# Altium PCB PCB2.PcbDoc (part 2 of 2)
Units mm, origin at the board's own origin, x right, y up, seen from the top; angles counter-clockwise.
Board outline 159.99 x 100 mm, 12 copper layers (TopLayer, VCC, GROUND, MidLayer1, MidLayer2, MidLayer3, MidLayer4, MidLayer5, MidLayer6, MidLayer7, MidLayer8, BottomLayer); 300 components, 468 nets, 2269 pads, 42 vias.
Unrouted connection lines stored in the file: 456.
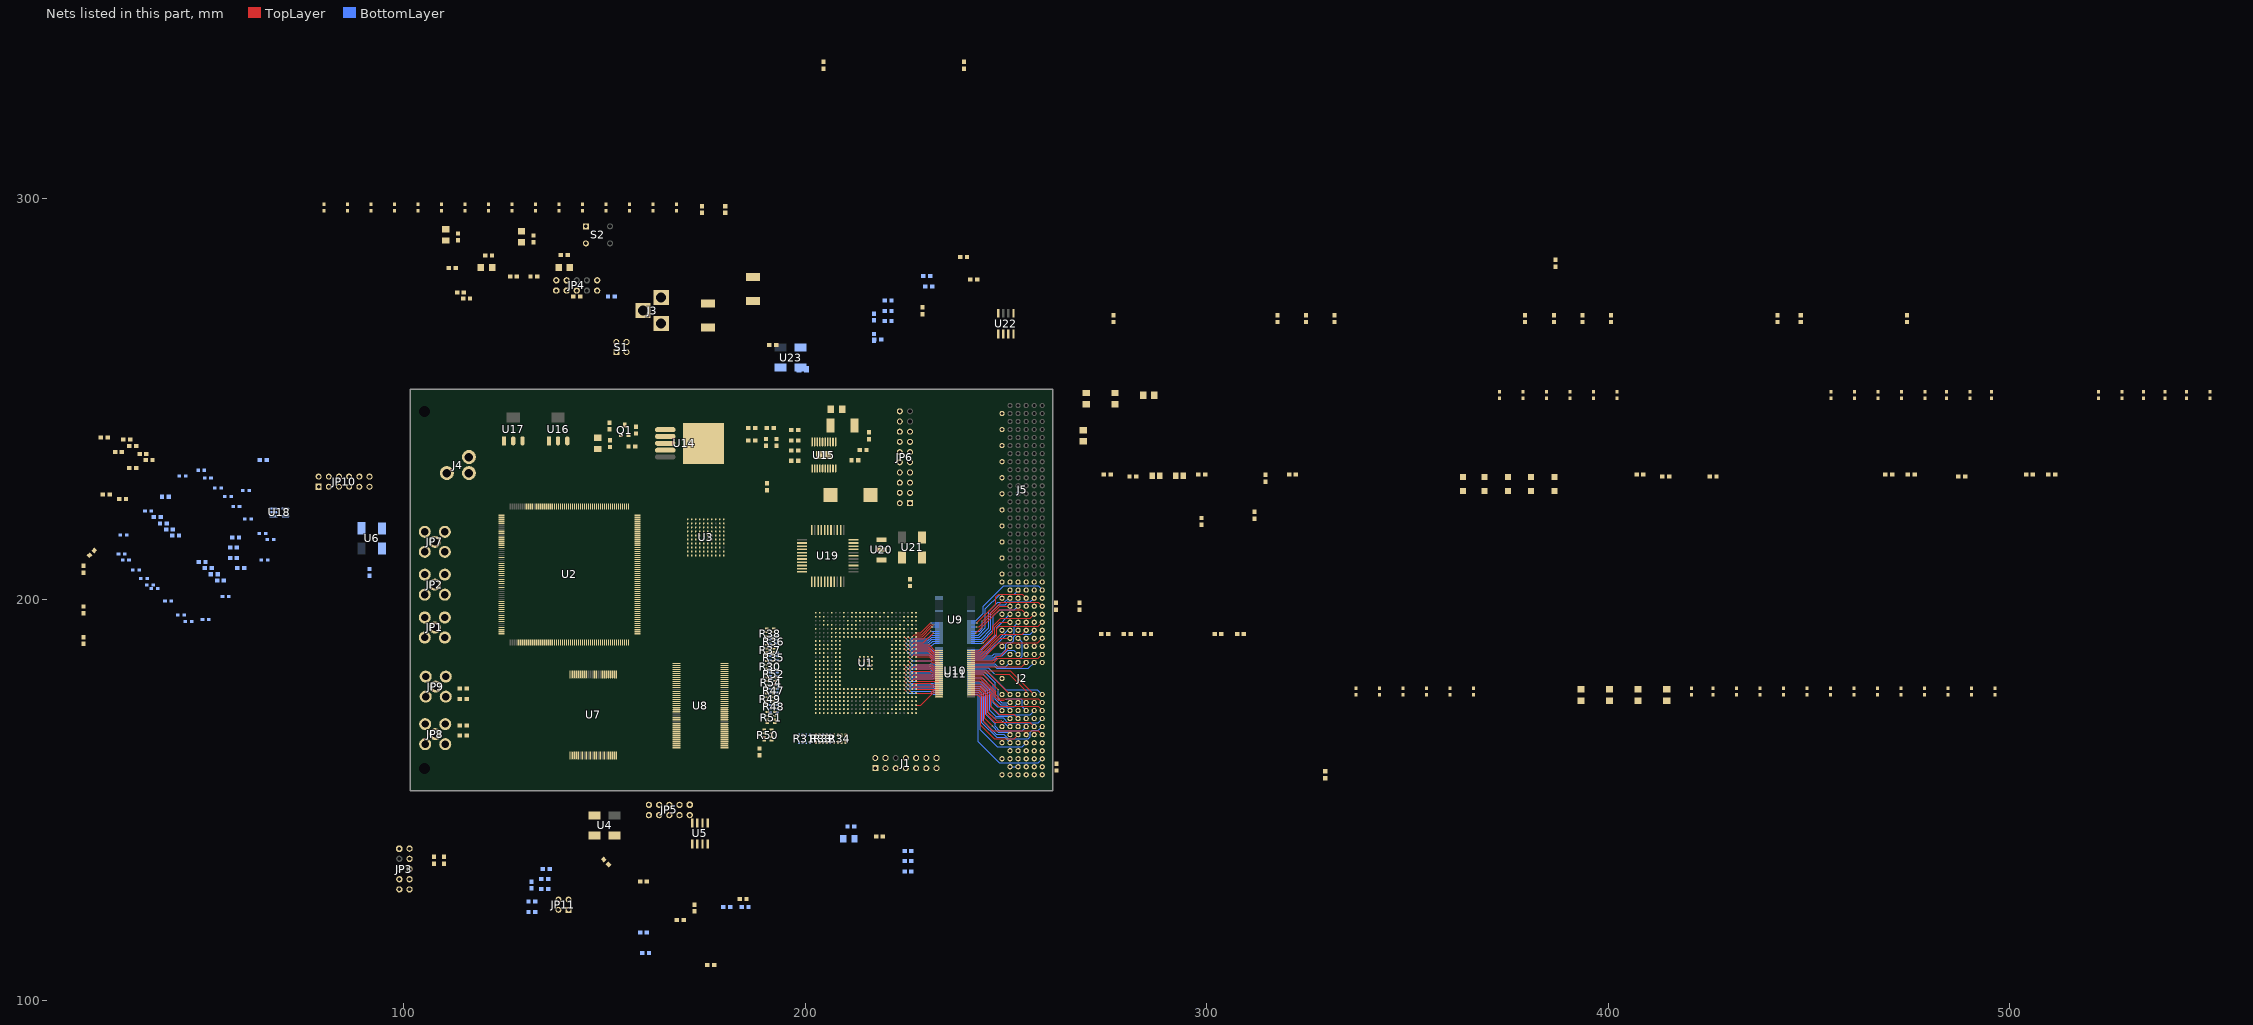
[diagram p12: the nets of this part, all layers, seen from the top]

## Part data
C1 C2 C3 C4 C5 C6 C7 C8 C9 C10 C11 C12 C13 C14 C15 C16 C17 C18 C19 C20 C21 C22 C23 C24 C25 C26 C27 C28 C29 C30 C32 C36 C37 C38 C39 C40 C41 C42 C43 C44 C45 C46 C47 C48 C49 C50 C51 C52 C53 C54 C55 C56 C57 C58 C59 C60 C61 C62 C63 C64 C65 C66 C67 C68 C69 C70 C71 C72 C73 C74 C75 C76 C77 C78 C79 C80 C81 C82 C83 C84 C85 C86 C87 C88 C89 C90 C91 C92 C93 C94 C95 C96 C97 C98 C99 C100 C101 C102 C103 C104 C105 C106 C107 C108 C109 C110 C111 C112 C113 C114 C115 C116 C117 C118 C119 C120 C121 C122 C123 C124 C125 C126 C127 C128 C129 C130 C131 C132 C133 C153 C154 C155 C156 C157 C158 C159 C160 C161 C162 C163 C165 C166: "Capacitor"
C134 C135 C136 C137 C138 C139 C140 C141 C142 C143: "Polarized Capacitor (Radial)"
C144 C145 C146 C147 C148 C149 C150 C151 C152 C164: "Polarized Capacitor (Axial)"
DS1 DS2 DS3 DS4 DS5: "Typical RED, GREEN, YELLOW, AMBER GaAs LED"
DS6 DS7 DS9: "Typical BLUE SiC LED"
FB1 FB2 FB3: library part Inductor, "Inductor"
J1: library part "Header 7X2", "Header, 7-Pin, Dual row"
J2: library part 352495-1, "Z-Pack 2mm Hard Metric Type A 154 Position Male PCB Mount Connector"
J4: "RCA Connector"
J5: "Z-Pack 2mm Hard Metric Type B 110 Position Female Daughter Card Connector"
JP1 JP2 JP7 JP8 JP9: "Header, 2-Pin"
JP3 JP4 JP5: library part "Header 5X2", "Header, 5-Pin, Dual row"
JP6: "Header, 10-Pin, Dual row"
JP10: "Header, 6-Pin, Dual row"
JP11: "Header, 2-Pin, Dual row"
L1: "Magnetic-Core Inductor"
Q1: library part QNPN, "NPN Bipolar Transistor"
R1 R2 R3 R4 R5 R6 R7 R8 R9 R10 R11 R12 R13 R14 R15 R16 R17 R18 R19 R20 R21 R22 R23 R24 R25 R26 R27 R28 R29 R39 R40 R41 R42 R43 R44 R45 R46 R53 R55 R56 R57 R58 R59 R60 R61 R62 R63 R64 R65 R66 R67 R68 R69 R70 R71 R72 R73 R74 R76 R77 R78 R79 R80 R81 R82 R83 R84 R86 R87 R88: "Resistor"
R30 R31 R32 R33 R34 R35 R36 R37 R38 R47 R48 R49 R50 R51 R52 R54: "Resistor Array - Parts"
S1: "DIP Switch"
S2: "Switch"
U2: "Cyclone Family, 1.5V FPGA, 173 I/O Pins, 2 x PLLs, Commercial Grade, Speed Grade 6"
U3: "Hotlink II"
U4 U6: library part Oscillator
U5: "EPCS1 Series, In-system programmable 3.3V configuration device, 8-Pin SOIC, 1-Megabit, Industrial Grade"
U8: "by TX"
U16 U17: library part "Volt Reg", "Voltage Regulator"
U20: library part "EMI filter"

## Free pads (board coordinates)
  round 1.27 hole 2.794: 1(105.156,246.812) 2(105.156,157.912)

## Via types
v1: diameter 0.406, hole 0.203, TopLayer to BottomLayer, 40 vias
v2: diameter 1.44, hole 1.44, TopLayer to BottomLayer, 2 vias

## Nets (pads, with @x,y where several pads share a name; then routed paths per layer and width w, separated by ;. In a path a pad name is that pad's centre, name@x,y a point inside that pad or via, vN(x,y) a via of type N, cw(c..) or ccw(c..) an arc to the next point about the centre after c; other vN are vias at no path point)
1.4VPWRGD: R64.2 R72.2 U15.4
101_BISTLE: U2.12 U3.E1
101_BOE0: U2.14 U3.D1
101_BOE1: U2.15 U3.D2
101_DECOMDE: U2.8 U3.E2
101_FRAMCHAR: U2.13 U3.D3
101_INSEL: U2.195 U3.C10
101_L\F\I\: U2.227 U3.H4
101_LPEN: U2.17 U3.C2
101_OELE: U2.6 U3.E3
101_PARCTL: U2.186 U3.C8
101_REFCLK+: R13.2 U2.201
101_REFCLK-: R12.2 U2.202
101_RFEN: U2.16 U3.C1
101_RFMODE: U2.188 U3.C9
101_RXCKSEL: U2.200 U3.E9
101_RXCLK+: U2.233 U3.K4
101_RXCLK-: U2.228 U3.J4
101_RXCLKC+: U2.7 U3.C4
101_RXD0: U2.240 U3.H1
101_RXD1: U2.1 U3.G2
101_RXD2: U2.236 U3.H2
101_RXD3: U2.238 U3.J2
101_RXD4: U2.239 U3.K2
101_RXD5: U2.237 U3.G3
101_RXD6: U2.235 U3.H3
101_RXD7: U2.234 U3.J3
101_RXLE: U2.11 U3.C3
101_RXMODE: U2.19 U3.A5
101_RXOP: U2.2 U3.G1
101_RXRATE: U2.193 U3.C5
101_RXST0: U2.3 U3.F3
101_RXST1: U2.4 U3.F2
101_RXST2: U2.5 U3.F1
101_SCSEL: U2.215 U3.K9
101_SDASEL: U2.187 U3.C6
101_SPDSEL: U2.185 U3.C7
101_T\R\S\T\Z\: JP3.8 U2.196 U3.D9
101_T\X\R\S\T\: U2.213 U3.H9
101_TCK: JP3.4 U3.E8
101_TDI: JP3.6 U3.D10
101_TDO: JP3.9 U3.B3
101_TMS: JP3.2 U3.D8
101_TXCKSEL: U2.197 U3.E10
101_TXCLK: U2.208 U3.H8
101_TXCLKO+: U2.207 U3.G9
101_TXCLKO-: U2.206 U3.G10
101_TXCT0: U2.225 U3.J5
101_TXCT1: U2.224 U3.H5
101_TXD0: U2.216 U3.J8
101_TXD1: U2.218 U3.K7
101_TXD2: U2.217 U3.J7
101_TXD3: U2.214 U3.H7
101_TXD4: U2.223 U3.K6
101_TXD5: U2.222 U3.J6
101_TXD6: U2.219 U3.H6
101_TXD7: U2.226 U3.K5
101_TXMODE0: U2.20 U3.B6
101_TXMODE1: U2.21 U3.A6
101_TXOP: U2.203 U3.G8
101_TXPER: U2.194 U3.F8
101_TXRATE: U2.18 U3.B5
AGND2: C153.1 C155.1 C157.1 C159.1 J4.2 R41.1 U19.32 U19.33
AOE#: R52.6 U2.50 U8.19
ARE#: R52.5 U2.53 U7.28 U8.18
AS_CONFDN: JP5.3 R26.1 U2.145
AS_DCLK: JP5.1 U2.36 U5.6
AS_NCONFIG: JP5.5 R27.1 U2.26
AWE#: R30.7 U2.54 U7.11 U8.17
BE0#: R47.5 U2.45 U8.16
BE1#: R47.6 U2.43 U8.71
BE2#: R54.7 U2.47 U8.28
BE3#: R54.8 U2.49 U8.59
CE0#: R30.8 U8.20
CE1#: R52.7 U7.26
CE2#: R52.8 U2.48
CE3#: U1.L26 U2.23
CVBS: J4.1 R40.2 R41.2
DATA: JP5.7 U2.25 U5.2
DSP_CLKIN: R82.2 U1.AC2
DSP_T\R\S\T\: J1.2 U1.D14
DSP_TCLK: J1.9 J1.11 U1.A16
DSP_TDI: J1.3 U1.A18
DSP_TDO: J1.7 U1.B18
DSP_TMS: J1.1 U1.E15
EA03: R47.7 U2.77 U7.45 U8.25
EA04: R47.8 U2.76 U7.25 U8.26
EA05: R54.6 U2.46 U7.24 U8.27
EA06: R48.5 U2.39 U7.23 U8.60
EA07: R48.6 U2.38 U7.22 U8.61
EA08: R54.5 U2.44 U7.21 U8.62
EA09: R48.7 U2.37 U7.20 U8.63
EA10: R48.8 U2.24 U7.19 U8.64
EA11: R49.8 U2.42 U7.18 U8.65
EA12: R49.7 U2.41 U7.8 U8.66
EA13: R49.6 U7.7 U8.24
EA14: R49.5 U7.6 U8.21
EA15: R51.8 U7.5 U8.22
EA16: R51.7 U7.4 U8.23
EA17: R50.5 U7.3
EA18: R50.8 U7.2
EA19: R51.6 R59.2 U7.1
EA20: R51.5 R58.1 U7.48
EA21: R50.7 S1.3 U7.17
EA22: R50.6 S1.4 U7.16
ECLKIN: U1.H25 U2.57
ECLKOUT1: R55.2 U8.68
ECLKOUT2: U1.J23 U2.29
ED00: R31.5 U2.78 U7.29 U8.2
ED01: R31.6 U2.98 U7.31 U8.4
ED02: R31.7 U2.95 U7.33 U8.5
ED03: R33.8 U2.79 U7.35 U8.7
ED04: R33.7 U2.83 U7.38 U8.8
ED05: R31.8 U2.85 U7.40 U8.10
ED06: R33.6 U2.84 U7.42 U8.11
ED07: R32.5 U2.82 U7.44 U8.13
ED08: R33.5 U2.87 U8.74
ED09: R32.6 U2.86 U8.76
ED10: R34.8 U2.88 U8.77
ED11: R32.7 U2.93 U8.79
ED12: R34.7 U2.99 U8.80
ED13: R32.8 U2.94 U8.82
ED14: R34.5 U2.101 U8.83
ED15: R34.6 U2.100 U8.85
ED16: R35.8 U2.55 U8.31
ED17: R35.7 U2.56 U8.33
ED18: R37.5 U2.62 U8.34
ED19: R36.8 U2.63 U8.36
ED20: R35.6 U2.58 U8.37
ED21: R35.5 U2.59 U8.39
ED22: R37.6 U2.60 U8.40
ED23: R36.6 U2.65 U8.42
ED24: R37.7 U2.61 U8.45
ED25: R36.7 U2.64 U8.47
ED26: R37.8 U2.66 U8.48
ED27: R36.5 U2.67 U8.50
ED28: R38.6 U2.68 U8.51
ED29: R38.5 U2.73 U8.53
ED30: R38.8 U2.74 U8.54
ED31: R38.7 U2.75 U8.56
EMU0: J1.13 U1.A15
EMU1: J1.14 U1.C14
FPGA_ASDO: JP5.9 U5.5
FPGA_NCSO: JP5.8 U5.1
GCLK0: R25.2 U2.153
GCLK1: R24.2 U2.28
GND: C5.1 C6.1 C7.1 C8.1 C9.1 C10.1 C11.1 C12.1 C13.1 C14.1 C15.1 C16.1 C17.1 C18.1 C19.1 C20.1 C21.1 C22.1 C23.1 C24.1 C25.1 C26.1 C32.1 C36.1 C37.2 C38.2 C39.2 C40.2 C41.2 C45.2 C46.2 C47.2 C48.2 C49.2 C54.1 C55.2 C56.2 C57.2 C58.2 C59.2 C64.1 C65.2 C66.2 C67.2 C68.2 C69.2 C73.2 C74.2 C75.2 C76.2 C77.2 C82.2 C83.2 C84.2 C85.2 C86.2 C95.1 C96.1 C97.2 C98.2 C99.2 C100.2 C101.2 C103.2 C104.2 C105.2 C106.2 C107.2 C108.2 C109.2 C110.2 C111.2 C112.2 C114.2 C115.2 C116.2 C117.2 C119.2 C120.2 C121.2 C123.2 C124.2 C125.1 C126.1 C127.1 C128.1 C129.1 C130.1 C131.1 C132.1 C133.1 C134.2 C135.2 C136.2 C137.2 C138.2 C139.2 C140.2 C141.2 C142.2 C143.2 C144.2 C146.2 C147.2 C150.2 C152.2 C154.1 C156.1 C158.1 C160.1 C161.1 C162.1 C163.1 C164.2 C165.1 C166.1 DS6.2 DS7.2 DS9.2 J1.4 J1.8 J1.10 J1.12 J2.B6 J2.B8 J2.B10 J2.B16 J2.B18 J2.B20 J2.B22 J2.D5 J2.D7 J2.D9 J2.D11 J2.D17 J2.D19 J2.F1 J2.F3 J2.F5 J2.F7 J2.F9 J2.F11 J2.F13 J2.F15 J2.F17 J2.F19 J2.F21 J2.F23 J2.F25 J3.2 J3.3 J5.F1 J5.F3 J5.F5 J5.F7 J5.F9 J5.F11 J5.F13 J5.F15 J5.F17 J5.F19 J5.F21 JP3.1 JP3.10 JP4.2 JP4.10 JP5.2 JP5.10 Q1.3 R15.2 R17.1 R18.2 R19.2 R20.2 R21.2 R22.1 R23.1 R28.1 R39.2 R59.1 R60.1 R65.1 R67.1 R83.1 R84.1 S2.1 U1.A1 U1.A3 U1.A6 U1.A8 U1.A12 U1.A14 U1.A19 U1.A22 U1.A26 U1.AA4 U1.AA5 U1.AA8 U1.AA10 U1.AA11 U1.AA13 U1.AA14 U1.AA16 U1.AA17 U1.AA19 U1.AA22 U1.AB1 U1.AB2 U1.AB4 U1.AB6 U1.AB9 U1.AB18 U1.AB21 U1.AB26 U1.AC3 U1.AC5 U1.AC18 U1.AC22 U1.AC24 U1.AD2 U1.AD4 U1.AD18 U1.AE3 U1.AE8 U1.AE10 U1.AE12 U1.AE14 U1.AE19 U1.AE24 U1.AF1 U1.AF7 U1.AF9 U1.AF11 U1.AF13 U1.AF15 U1.AF19 U1.AF22 U1.AF26 U1.B3 U1.B6 U1.B7 U1.B13 U1.B19 U1.C2 U1.C4 U1.C13 U1.C18 U1.C23 U1.D1 U1.D2 U1.D5 U1.D13 U1.D18 U1.D22 U1.D24 U1.E3 U1.E6 U1.E9 U1.E16 U1.E18 U1.E21 U1.E23 U1.E26 U1.F5 U1.F8 U1.F10 U1.F11 U1.F13 U1.F14 U1.F16 U1.F17 U1.F19 U1.F22 U1.G9 U1.G12 U1.G15 U1.G18 U1.H1 U1.H6 U1.H21 U1.H26 U1.J5 U1.J7 U1.J20 U1.J22 U1.K6 U1.K21 U1.L1 U1.L6 U1.L21 U1.M7 U1.M13 U1.M15 U1.M20 U1.N5 U1.N6 U1.N12 U1.N14 U1.N21 U1.N25 U1.P2 U1.P6 U1.P13 U1.P15 U1.P21 U1.R7 U1.R12 U1.R14 U1.R20 U1.T1 U1.T5 U1.T6 U1.T21 U1.T26 U1.U6 U1.U21 U1.V5 U1.V7 U1.V20 U1.V22 U1.W1 U1.W6 U1.W21 U1.W26 U1.Y9 U1.Y12 U1.Y15 U1.Y18 U2.10 U2.30 U2.31 U2.40 U2.52 U2.69 U2.71 U2.80 U2.89 U2.91 U2.96 U2.102 U2.109 U2.111 U2.129 U2.142 U2.150 U2.151 U2.171 U2.190 U2.192 U2.199 U2.205 U2.210 U2.212 U2.221 U2.230 U2.232 U3.D4 U3.D5 U3.D6 U3.D7 U3.E4 U3.E5 U3.E6 U3.E7 U3.F4 U3.F5 U3.F6 U3.F7 U3.G4 U3.G5 U3.G6 U3.G7 U4.2 U5.4 U6.2 U7.27 U7.46 U7.47 U8.6 U8.12 U8.32 U8.38 U8.44 U8.46 U8.52 U8.58 U8.72 U8.78 U8.84 U8.86 U9.8 U9.17 U9.32 U9.41 U9.47 U9.48 U10.8 U10.17 U10.32 U10.41 U10.47 U10.48 U11.8 U11.17 U11.32 U11.41 U11.47 U11.48 U14.3 U15.1 U15.11 U15.12 U15.13 U16.2 U17.2 U18.2 U19.2 U19.3 U19.5 U19.18 U19.19 U19.35 U19.38 U19.44 U20.2 U21.2 U22.5 U23.2
GP02: R86.1 U1.C6
GP04: U1.F4 U2.104
GP05: U1.F3 U2.107
GP06: U1.F2 U2.106
GP07: U1.E1 U2.105
IN1+: C2.1 R11.1 U3.A7
IN1-: C1.1 R11.2 U3.B7
IN2+: C30.1 R53.1 U3.A2
IN2-: C29.1 R8.1 R53.2 U3.B2
JTAG_TCK: JP4.1 R17.2 U2.147
JTAG_TDI: JP4.9 R14.1 U2.155
JTAG_TDO: JP4.3 U2.149
JTAG_TMS: JP4.5 R16.1 U2.148
LVDS1_INN: JP1.1 R43.1 U2.179
LVDS1_INP: JP1.2 R43.2 U2.180
LVDS1_OUTN: JP10.3 R7.1 R10.1
LVDS1_OUTP: JP10.1 R7.2 R9.1
LVDS2_INN: JP2.1 R42.1 U2.177
LVDS2_INP: JP2.2 R42.2 U2.178
LVDS2_OUTN: JP10.7 R4.1 R6.1
LVDS2_OUTP: JP10.5 R4.2 R5.1
LVDS3_INN: JP7.1 R77.1 U2.173
LVDS3_INP: JP7.2 R77.2 U2.174
LVDS3_OUTN: JP10.11 R1.1 R3.1
LVDS3_OUTP: JP10.9 R1.2 R2.1
LVDS4_INN: JP10.12 R44.1 U2.168
LVDS4_INP: JP10.10 R44.2 U2.169
LVDS5_INN: JP10.8 R45.1 U2.166
LVDS5_INP: JP10.6 R45.2 U2.167
LVDS6_INN: JP10.4 R46.1 U2.164
LVDS6_INP: JP10.2 R46.2 U2.165
NCE: JP5.6 R28.2 U2.33
NCEO: U2.32
NetC27_1: C27.1 JP11.1
NetC28_1: C28.1 JP11.2
NetC29_2: C29.2 JP11.3
NetC30_2: C30.2 JP11.4
NetC42_2: C42.2 C43.2 C44.2 C50.2 C51.2 C52.2 C53.2 C60.2 C61.2 C62.2 C63.1 C70.2 C71.2 C72.2 C78.1 C79.2 C80.2 C81.2 C87.2 C88.2 C89.2 C90.1 C91.1 C92.1 C93.1 C94.1 C145.2 C148.2 C149.2 C151.2
NetC54_2: C54.2 U15.18
NetC64_2: C64.2 U15.17
NetC102_1: C102.1 U15.5
NetC102_2: C102.2 L1.1 U15.6 U15.7 U15.8 U15.9 U15.10
NetC113_1: C113.1 C118.1 C122.1 R67.2 R70.1 U15.2
NetC113_2: C113.2 R68.1
NetC118_2: C118.2 R68.2 U15.3
NetC122_2: C122.2 R69.1
NetC160_2: C160.2 C161.2 FB3.2 U21.4
NetC163_2: C163.2 C164.1 U1.V6 U20.3
NetDS1_2: DS1.2 R15.1
NetDS2_2: DS2.2 R18.1
NetDS3_2: DS3.2 R19.1
NetDS4_2: DS4.2 R20.1
NetDS5_2: DS5.2 R21.1
NetDS6_1: DS6.1 R62.1
NetDS7_1: DS7.1 R63.1
NetDS9_1: DS9.1 R86.2
NetQ1_1: Q1.1 R73.1 U14.1
NetQ1_2: Q1.2 R72.1
NetR2_2: R2.2 U2.133
NetR3_2: R3.2 U2.132
NetR5_2: R5.2 U2.135
NetR6_2: R6.2 U2.134
NetR9_2: R9.2 U2.137
NetR10_2: R10.2 U2.136
NetR12_1: R12.1 U3.F9
NetR13_1: R13.1 U3.F10
NetR22_2: R22.2 U2.34
NetR23_2: R23.2 U2.35
NetR24_1: R24.1 U4.3
NetR25_1: R25.1 U6.3
NetR30_1: R30.1 U1.K25
NetR30_2: R30.2 U1.K26
NetR30_3: R30.3 U1.L25
NetR31_1: R31.1 U1.A23
NetR31_2: R31.2 U1.B23
NetR31_3: R31.3 U1.A24
NetR31_4: R31.4 U1.B24
NetR32_1: R32.1 U1.A20
NetR32_2: R32.2 U1.B20
NetR32_3: R32.3 U1.A21
NetR32_4: R32.4 U1.B21
NetR33_1: R33.1 U1.B22
NetR33_2: R33.2 U1.C22
NetR33_3: R33.3 U1.C21
NetR33_4: R33.4 U1.D21
NetR34_1: R34.1 U1.C20
NetR34_2: R34.2 U1.D20
NetR34_3: R34.3 U1.C19
NetR34_4: R34.4 U1.D19
NetR35_1: R35.1 U1.H24
NetR35_2: R35.2 U1.H23
NetR35_3: R35.3 U1.G25
NetR35_4: R35.4 U1.G24
NetR36_1: R36.1 U1.G23
NetR36_2: R36.2 U1.F24
NetR36_3: R36.3 U1.F23
NetR36_4: R36.4 U1.E24
NetR37_1: R37.1 U1.E25
NetR37_2: R37.2 U1.F25
NetR37_3: R37.3 U1.F26
NetR37_4: R37.4 U1.G26
NetR38_1: R38.1 U1.C25
NetR38_2: R38.2 U1.C26
NetR38_3: R38.3 U1.D25
NetR38_4: R38.4 U1.D26
NetR39_1: R39.1 U19.21
NetR40_1: R40.1 U19.30
NetR47_1: R47.1 U1.M23
NetR47_2: R47.2 U1.M24
NetR47_3: R47.3 U1.L23
NetR47_4: R47.4 U1.L24
NetR48_1: R48.1 U1.P23
NetR48_2: R48.2 U1.P24
NetR48_3: R48.3 U1.N23
NetR48_4: R48.4 U1.N24
NetR49_1: R49.1 U1.R24
NetR49_2: R49.2 U1.R23
NetR49_3: R49.3 U1.T25
NetR49_4: R49.4 U1.T24
NetR50_1: R50.1 U1.V23
NetR50_2: R50.2 U1.V24
NetR50_3: R50.3 U1.U23
NetR50_4: R50.4 U1.U24
NetR51_1: R51.1 U1.U26
NetR51_2: R51.2 U1.U25
NetR51_3: R51.3 U1.V26
NetR51_4: R51.4 U1.V25
NetR52_1: R52.1 U1.K23
NetR52_2: R52.2 U1.K24
NetR52_3: R52.3 U1.J24
NetR52_4: R52.4 U1.J25
NetR54_1: R54.1 U1.M25
NetR54_2: R54.2 U1.M26
NetR54_3: R54.3 U1.N26
NetR54_4: R54.4 U1.P26
NetR55_1: R55.1 U1.J26
NetR56_2: R56.2 S1.1
NetR57_2: R57.2 S1.2
NetR65_2: R65.2 U15.20
NetR66_1: R66.1 U15.19
NetR76_1: R76.1 U23.3
NetR79_2: R79.2 U1.B4
NetR80_1: R80.1 U1.AE4
NetR81_1: R81.1 U18.4
NetR81_2: R81.2 R83.2 U1.C5
NetR82_1: R82.1 U21.3
NetR84_2: R84.2 U1.B5
NetS2_2: S2.2 U18.3
NSTATUS: R29.1 U2.146
OUT1+: C3.1 U3.B9
OUT1-: C4.1 U3.A9
OUT2+: C28.2 U3.A4
OUT2-: C27.2 U3.B4
P\C\I\6\6\: R74.1 U1.AD1
P_AD0: U1.Y3 U9.29 | length 8.3
  TopLayer w0.152: U1.Y3@225.584,190.704 v1(226.111,190.195)
  BottomLayer w0.152: v1(226.111,190.195) 230.353,190.195 231.317,191.16 U9.29@233.3,191.16
P_AD1: U1.AA1 U9.35 | length 6.7
  TopLayer w0.152: U1.AA1@227.584,191.704 228.737,191.704 v1(231.193,194.16)
  BottomLayer w0.152: v1(231.193,194.16) U9.35@233.3,194.16
P_AD2: U1.Y4 U9.28 | length 9.5
  TopLayer w0.152: U1.Y4@224.584,190.704 v1(225.093,190.195)
  BottomLayer w0.152: v1(225.093,190.195) 225.55,189.738 230.505,189.738 231.427,190.66 U9.28@233.3,190.66
P_AD3: U1.Y2 U9.34 | length 8
  TopLayer w0.152: U1.Y2@226.584,190.704 227.066,191.186 228.93,191.186 231.419,193.675 v1(231.902,193.675)
  BottomLayer w0.152: v1(231.902,193.675) 233.285,193.675 U9.34@233.3,193.66
P_AD4: U1.W3 U9.27 | length 8.3
  TopLayer w0.152: U1.W3@225.584,189.704 v1(226.058,189.23)
  BottomLayer w0.152: v1(226.058,189.23) 230.607,189.23 231.537,190.16 U9.27@233.3,190.16
P_AD5: U1.Y1 U9.33 | length 6.7
  TopLayer w0.152: U1.Y1@227.584,190.704 229.083,190.704 v1(231.539,193.16)
  BottomLayer w0.152: v1(231.539,193.16) U9.33@233.3,193.16
P_AD6: U1.W4 U9.26 | length 9.5
  TopLayer w0.152: U1.W4@224.584,189.704 v1(225.058,189.23)
  BottomLayer w0.152: v1(225.058,189.23) 225.566,188.722 230.759,188.722 231.697,189.66 U9.26@233.3,189.66
P_AD7: U1.W2 U9.31 | length 7.7
  TopLayer w0.152: U1.W2@226.584,189.704 227.101,190.221 229.311,190.221 v1(231.251,192.16)
  BottomLayer w0.152: v1(231.251,192.16) U9.31@233.3,192.16
P_AD8: U1.V2 U9.30 | length 7.9
  TopLayer w0.152: U1.V2@226.584,188.704 227.11,189.23 229.387,189.23 v1(231.817,191.66)
  BottomLayer w0.152: v1(231.817,191.66) U9.30@233.3,191.66
P_AD9: U1.V3 U9.25 | length 8.3
  TopLayer w0.152: U1.V3@225.584,188.704 v1(226.074,188.214)
  BottomLayer w0.152: v1(226.074,188.214) 231.115,188.214 232.061,189.16 U9.25@233.3,189.16
P_AD10: U1.V1 U11.25 | length 6.3
  TopLayer w0.152: U1.V1@227.584,188.704 230.802,188.704 232.238,187.268 U11.25@233.3,187.268
P_AD11: U1.U4 U10.44 | length 9.4
  TopLayer w0.152: U1.U4@224.584,187.704 v1(225.09,187.198)
  BottomLayer w0.152: v1(225.09,187.198) 225.547,186.741 230.886,186.741 231.667,185.96 U10.44@233.3,185.96
P_AD12: U1.U2 U11.26 | length 7.5
  TopLayer w0.152: U1.U2@226.584,187.704 227.094,188.214 230.556,188.214 232.002,186.768 U11.26@233.3,186.768
P_AD13: U1.U3 U10.45 | length 8.2
  TopLayer w0.152: U1.U3@225.584,187.704 v1(226.09,187.198)
  BottomLayer w0.152: v1(226.09,187.198) 231.038,187.198 231.776,186.46 U10.45@233.3,186.46
P_AD14: U1.U1 U11.27 | length 6.3
  TopLayer w0.152: U1.U1@227.584,187.704 230.558,187.704 231.994,186.268 U11.27@233.3,186.268
P_AD15: U1.T3 U10.43 | length 8.2
  TopLayer w0.152: U1.T3@225.584,186.704 v1(226.055,186.233)
  BottomLayer w0.152: v1(226.055,186.233) 230.683,186.233 231.456,185.46 U10.43@233.3,185.46
P_AD16: U1.M3 U10.37 | length 8
  TopLayer w0.152: U1.M3@225.584,182.704 v1(226.094,182.194)
  BottomLayer w0.152: v1(226.094,182.194) 231.216,182.194 231.482,182.46 U10.37@233.3,182.46
P_AD17: U1.M2 U11.34 | length 7.1
  TopLayer w0.152: U1.M2@226.584,182.704 227.09,183.21 231.394,183.21 231.836,182.768 U11.34@233.3,182.768
P_AD18: U1.M4 U10.36 | length 9.2
  TopLayer w0.152: U1.M4@224.584,182.704 v1(225.094,182.194)
  BottomLayer w0.152: v1(225.094,182.194) 225.551,181.737 231.394,181.737 231.617,181.96 U10.36@233.3,181.96
P_AD19: U1.L2 U11.36 | length 7.1
  TopLayer w0.152: U1.L2@226.584,181.704 227.074,182.194 231.038,182.194 231.465,181.768 U11.36@233.3,181.768
P_AD20: U1.L3 U10.35 | length 8
  TopLayer w0.152: U1.L3@225.584,181.704 v1(226.059,181.229)
  BottomLayer w0.152: v1(226.059,181.229) 231.572,181.229 231.803,181.46 U10.35@233.3,181.46
P_AD21: U1.K2 U11.37 | length 6.9
  TopLayer w0.152: U1.K2@226.584,180.704 227.109,181.229 233.261,181.229 U11.37@233.3,181.268
P_AD22: U1.L4 U10.34 | length 9.2
  TopLayer w0.152: U1.L4@224.584,181.704 v1(225.059,181.229)
  BottomLayer w0.152: v1(225.059,181.229) 225.567,180.721 231.623,180.721 231.862,180.96 U10.34@233.3,180.96
P_AD23: U1.K1 U11.38 | length 5.7
  TopLayer w0.152: U1.K1@227.584,180.704 233.236,180.704 U11.38@233.3,180.768
P_AD24: U1.K4 U10.31 | length 9.2
  TopLayer w0.152: U1.K4@224.584,180.704 v1(225.075,180.213)
  BottomLayer w0.152: v1(225.075,180.213) 225.583,179.705 231.826,179.705 232.071,179.46 U10.31@233.3,179.46
P_AD25: U1.J1 U11.40 | length 5.7
  TopLayer w0.152: U1.J1@227.584,179.704 233.236,179.704 U11.40@233.3,179.768
P_AD26: U1.J3 U10.30 | length 8
  TopLayer w0.152: U1.J3@225.584,179.704 v1(226.091,179.197)
  BottomLayer w0.152: v1(226.091,179.197) 231.851,179.197 232.088,178.96 U10.30@233.3,178.96
P_AD27: U1.H2 U11.42 | length 7.1
  TopLayer w0.152: U1.H2@226.584,178.704 227.077,179.197 230.988,179.197 231.417,178.768 U11.42@233.3,178.768
P_AD28: U1.J4 U10.29 | length 9.2
  TopLayer w0.152: U1.J4@224.584,179.704 v1(225.091,179.197)
  BottomLayer w0.152: v1(225.091,179.197) 225.548,178.74 231.699,178.74 231.979,178.46 U10.29@233.3,178.46
P_AD29: U1.G2 U11.43 | length 6.9
  TopLayer w0.152: U1.G2@226.584,177.704 227.112,178.232 233.264,178.232 U11.43@233.3,178.268
P_AD30: U1.H3 U10.28 | length 8
  TopLayer w0.152: U1.H3@225.584,178.704 v1(226.056,178.232)
  BottomLayer w0.152: v1(226.056,178.232) 231.775,178.232 232.047,177.96 U10.28@233.3,177.96
P_AD31: U1.G1 U11.44 | length 5.7
  TopLayer w0.152: U1.G1@227.584,177.704 233.236,177.704 U11.44@233.3,177.768
P_CBE0: U1.V4 U10.46 | length 9.4
  TopLayer w0.152: U1.V4@224.584,188.704 v1(225.074,188.214)
  BottomLayer w0.152: v1(225.074,188.214) 225.582,187.706 231.191,187.706 231.937,186.96 U10.46@233.3,186.96
P_CBE1: U1.T2 U11.28 | length 7.5
  TopLayer w0.152: U1.T2@226.584,186.704 227.078,187.198 230.48,187.198 231.91,185.768 U11.28@233.3,185.768
P_CBE2: U1.M1 U11.35 | length 5.9
  TopLayer w0.152: U1.M1@227.584,182.704 231.316,182.704 231.752,182.268 U11.35@233.3,182.268
P_CBE3: U1.J2 U11.39 | length 6.9
  TopLayer w0.152: U1.J2@226.584,179.704 227.093,180.213 233.245,180.213 U11.39@233.3,180.268
P_CLK: U1.C1 U11.46 | length 7
  TopLayer w0.152: U1.C1@227.584,173.704 228.746,173.704 231.81,176.768 U11.46@233.3,176.768
P_DEVSEL: U1.P1 U11.31 | length 5.9
  TopLayer w0.152: U1.P1@227.584,184.704 231.17,184.704 231.606,184.268 U11.31@233.3,184.268
P_EN: R61.1 U1.E2
P_FRAME: U1.N4 U10.38 | length 9.2
  TopLayer w0.152: U1.N4@224.584,183.704 v1(225.078,183.21)
  BottomLayer w0.152: v1(225.078,183.21) 225.586,182.702 231.115,182.702 231.372,182.96 U10.38@233.3,182.96
P_GNT: U1.H4 U10.27 | length 9.2
  TopLayer w0.152: U1.H4@224.584,178.704 v1(225.056,178.232)
  BottomLayer w0.152: v1(225.056,178.232) 225.564,177.724 231.699,177.724 231.963,177.46 U10.27@233.3,177.46
P_IDSEL: U1.K3 U10.33 | length 8
  TopLayer w0.152: U1.K3@225.584,180.704 v1(226.075,180.213)
  BottomLayer w0.152: v1(226.075,180.213) 231.826,180.213 232.073,180.46 U10.33@233.3,180.46
P_INTA: U1.G4 U10.25 | length 9.2
  TopLayer w0.152: U1.G4@224.584,177.704 v1(225.098,177.19)
  BottomLayer w0.152: v1(225.098,177.19) 225.58,176.708 231.572,176.708 231.82,176.46 U10.25@233.3,176.46
P_IRDY: U1.N1 U11.33 | length 5.9
  TopLayer w0.152: U1.N1@227.584,183.704 231.484,183.704 231.92,183.268 U11.33@233.3,183.268
P_PAR: U1.P3 U10.40 | length 8.2
  TopLayer w0.152: U1.P3@225.584,184.704 v1(226.087,184.201)
  BottomLayer w0.152: v1(226.087,184.201) 226.57,183.718 230.937,183.718 231.179,183.96 U10.40@233.3,183.96
P_PERR: U1.R1 U11.30 | length 6.1
  TopLayer w0.152: U1.R1@227.584,185.704 230.805,185.704 231.741,184.768 U11.30@233.3,184.768
P_REQ: U1.F1 U11.45 | length 5.9
  TopLayer w0.152: U1.F1@227.584,176.704 231.187,176.704 231.751,177.268 U11.45@233.3,177.268
P_RST: U1.G3 U10.26 | length 8
  TopLayer w0.152: U1.G3@225.584,177.704 v1(226.098,177.19)
  BottomLayer w0.152: v1(226.098,177.19) 231.724,177.19 231.955,176.96 U10.26@233.3,176.96
P_SERR: U1.R2 U11.29 | length 7.3
  TopLayer w0.152: U1.R2@226.584,185.704 227.087,186.207 230.861,186.207 231.8,185.268 U11.29@233.3,185.268
P_STOP: U1.R3 U10.42 | length 8.2
  TopLayer w0.152: U1.R3@225.584,185.704 v1(226.071,185.217)
  BottomLayer w0.152: v1(226.071,185.217) 226.579,184.709 231.47,184.709 231.721,184.96 U10.42@233.3,184.96
P_TRDY: U1.N3 U10.39 | length 8
  TopLayer w0.152: U1.N3@225.584,183.704 v1(226.078,183.21)
  BottomLayer w0.152: v1(226.078,183.21) 231.038,183.21 231.288,183.46 U10.39@233.3,183.46
PCI_EEAI: R78.1 U1.L5
PXI_3.3V: J2.A15 J2.A17 J2.A19 J2.A21 J2.A23 J2.C6 J2.C10 J2.C18 J2.C22 J2.D25
PXI_5V: J2.A1 J2.A25 J2.B2 J2.B24 J2.D3 J2.D23 J2.E1 J2.E25
PXI_+12V: J2.D1
PXI_-12V: J2.B1
PXI_ACK64#: J2.E24 JP6.9
PXI_AD0: J2.D24 U9.20 | length 19.3
  BottomLayer w0.152: U9.20@241.3,191.16 243.053,191.16 244.856,192.963 244.856,197.663 248.564,201.371 252.031,201.371 J2.D24@253.123,202.463
PXI_AD1: J2.A24 U9.13 | length 22.8
  BottomLayer w0.152: U9.13@241.3,194.66 242.437,194.66 244.34,196.562 244.34,198.315 249.403,203.378 257.962,203.378 J2.A24@259,202.34
PXI_AD2: J2.E23 U9.21 | length 16.1
  BottomLayer w0.152: U9.21@241.3,190.66 243.357,190.66 245.72,193.022 245.72,197.079 247.94,199.299 249.565,199.299 250.607,200.34 J2.E23@251,200.34
PXI_AD3: J2.C23 U9.14 | length 18.1
  TopLayer w0.152: v1(242.75,194.16) 247.421,198.831 247.421,200.635 248.133,201.346 253.994,201.346 J2.C23@255,200.34
  BottomLayer w0.152: U9.14@241.3,194.16 v1(242.75,194.16)
PXI_AD4: J2.B23 U9.22 | length 22.3
  BottomLayer w0.152: U9.22@241.3,190.16 243.815,190.16 246.228,192.573 246.228,196.698 248.232,198.702 249.73,198.702 250.444,199.415 256.075,199.415 J2.B23@257,200.34
PXI_AD5: J2.E22 U9.16 | length 11.8
  TopLayer w0.152: v1(242.715,193.16) 243.3,193.16 248.48,198.34 J2.E22@251,198.34
  BottomLayer w0.152: U9.16@241.3,193.16 v1(242.715,193.16)
PXI_AD6: J2.D22 U9.23 | length 17.3
  BottomLayer w0.152: U9.23@241.3,189.66 244.094,189.66 246.863,192.429 246.863,195.91 248.387,197.434 252.094,197.434 J2.D22@253,198.34
PXI_AD7: J2.A22 U9.18 | length 22.2
  TopLayer w0.152: v1(244.094,194.64) 248.793,199.339 258.001,199.339 J2.A22@259,198.34
  BottomLayer w0.152: U9.18@241.3,192.16 243.443,192.16 244.094,192.811 v1(244.094,194.64)
PXI_AD8: J2.C21 U9.19 | length 16.5
  TopLayer w0.152: v1(242.485,191.66) 248.234,197.409 253.931,197.409 J2.C21@255,196.34
  BottomLayer w0.152: U9.19@241.3,191.66 v1(242.485,191.66)
PXI_AD9: J2.B21 U9.24 | length 19.7
  TopLayer w0.152: v1(244.126,189.16) 246.641,191.675 246.641,193.352 248.666,195.377 256.037,195.377 J2.B21@257,196.34
  BottomLayer w0.152: U9.24@241.3,189.16 v1(244.126,189.16)
PXI_AD10: J2.E20 U11.24 | length 13.7
  TopLayer w0.152: U11.24@241.3,187.268 243.199,187.268 247.174,191.243 247.174,193.097 248.417,194.34 J2.E20@251,194.34
PXI_AD11: J2.D20 U10.4 | length 16
  BottomLayer w0.152: U10.4@241.3,186.46 245.159,186.46 249.987,191.287 251.638,191.287 251.993,191.643 251.993,193.333 J2.D20@253,194.34
PXI_AD12: J2.A20 U11.23 | length 21.9
  TopLayer w0.152: U11.23@241.3,186.768 243.461,186.768 247.615,190.922 247.615,192.675 248.285,193.345 258.005,193.345 J2.A20@259,194.34
PXI_AD13: J2.E19 U10.3 | length 11.9
  BottomLayer w0.152: U10.3@241.3,186.96 245.075,186.96 250.455,192.34 J2.E19@251,192.34
PXI_AD14: J2.C19 U11.22 | length 16.2
  TopLayer w0.152: U11.22@241.3,186.268 243.647,186.268 248.691,191.313 253.973,191.313 J2.C19@255,192.34
PXI_AD15: J2.B19 U10.5 | length 19.7
  BottomLayer w0.152: U10.5@241.3,185.96 246.567,185.96 247.04,186.433 248.892,186.433 249.936,187.477 249.936,188.9 250.393,189.357 251.536,189.357 251.968,189.789 251.968,190.678 252.628,191.338 255.998,191.338 J2.B19@257,192.34
PXI_AD16: J2.C11 U10.11 | length 16.9
  TopLayer w0.152: v1(247.167,181.381) 250.8,181.381 255,177.181 J2.C11@255,176.34
  BottomLayer w0.152: U10.11@241.3,182.96 245.589,182.96 v1(247.167,181.381)
PXI_AD17: J2.B11 U11.14 | length 18.2
  TopLayer w0.152: U11.14@241.3,182.268 251.072,182.268 J2.B11@257,176.34
PXI_AD18: J2.A11 U10.12 | length 20.2
  BottomLayer w0.152: U10.12@241.3,182.46 244.946,182.46 249.86,177.546 257.794,177.546 J2.A11@259,176.34
PXI_AD19: J2.E10 U11.12 | length 13.9
  TopLayer w0.152: U11.12@241.3,181.268 244.258,181.268 v1(248.031,177.495)
  BottomLayer w0.152: v1(248.031,177.495) 248.031,175.285 248.976,174.34 J2.E10@251,174.34
PXI_AD20: J2.D10 U10.13 | length 18.1
  BottomLayer w0.152: U10.13@241.3,181.96 244.608,181.96 247.294,179.273 247.294,175.194 248.641,173.848 250.078,173.848 250.596,173.33 251.99,173.33 J2.D10@253,174.34
PXI_AD21: J2.A10 U11.11 | length 20.8
  TopLayer w0.152: U11.11@241.3,180.768 243.691,180.768 247.447,177.013 247.447,176.301 248.437,175.311 258.029,175.311 J2.A10@259,174.34
PXI_AD22: J2.E9 U10.14 | length 16.1
  BottomLayer w0.152: U10.14@241.3,181.46 244.168,181.46 246.812,178.816 246.812,174.346 247.828,173.33 250.01,173.33 J2.E9@251,172.34
PXI_AD23: J2.C9 U11.10 | length 18.8
  TopLayer w0.152: U11.10@241.3,180.268 243.556,180.268 246.99,176.835 246.99,175.946 248.056,174.879 v1(249.784,174.879)
  BottomLayer w0.152: v1(249.784,174.879) 250.241,175.336 253.619,175.336 254.076,174.879 254.076,173.264 J2.C9@255,172.34
PXI_AD24: J2.E8 U10.18 | length 16.5
  BottomLayer w0.152: U10.18@241.3,179.46 244.11,179.46 245.872,177.698 245.872,172.466 247.447,170.891 250.449,170.891 J2.E8@251,170.34
PXI_AD25: J2.D8 U11.7 | length 16.8
  TopLayer w0.152: U11.7@241.3,178.768 243.609,178.768 246.153,176.223 246.153,173.455 248.234,171.374 251.966,171.374 J2.D8@253,170.34
PXI_AD26: J2.A8 U10.19 | length 25.3
  BottomLayer w0.152: U10.19@241.3,178.96 243.874,178.96 245.44,177.394 245.44,171.958 246.888,170.51 249.25,170.51 250.393,169.367 258.027,169.367 J2.A8@259,170.34
PXI_AD27: J2.E7 U11.6 | length 16.3
  TopLayer w0.152: U11.6@241.3,178.268 243.448,178.268 245.618,176.098 245.618,171.907 247.701,169.824 v1(249.098,169.824)
  BottomLayer w0.152: v1(249.098,169.824) 250.582,168.34 J2.E7@251,168.34
PXI_AD28: J2.C7 U10.20 | length 22.5
  BottomLayer w0.152: U10.20@241.3,178.46 243.688,178.46 244.983,177.165 244.983,171.425 247.32,169.088 247.32,168.377 248.336,167.361 254.021,167.361 J2.C7@255,168.34
PXI_AD29: J2.B7 U11.5 | length 22.3
  TopLayer w0.152: U11.5@241.3,177.768 243.389,177.768 245.161,175.997 245.161,171.425 247.193,169.393 255.947,169.393 J2.B7@257,168.34
PXI_AD30: J2.A7 U10.21 | length 29.1
  BottomLayer w0.152: U10.21@241.3,177.96 243.35,177.96 244.475,176.835 244.475,169.545 247.574,166.446 249.479,166.446 250.571,165.354 255.575,165.354 255.981,165.76 255.981,166.903 256.464,167.386 258.046,167.386 J2.A7@259,168.34
PXI_AD31: J2.E6 U11.4 | length 17.4
  TopLayer w0.152: U11.4@241.3,177.268 243.178,177.268 244.627,175.819 244.627,170.383 v1(246.507,168.504)
  BottomLayer w0.152: v1(246.507,168.504) 248.107,166.903 250.437,166.903 J2.E6@251,166.34
PXI_BD_SEL#: J2.D15 JP6.5
PXI_BRSVP1A5: J2.A5
PXI_BRSVP1A6: JP6.2
PXI_BRSVP1B5: J2.B5
PXI_BRSVP1B6: JP6.12
PXI_C/BE0#: J2.E21 U10.2 | length 14.5
  BottomLayer w0.152: U10.2@241.3,187.46 243.764,187.46 247.675,191.372 247.675,193.015 J2.E21@251.078,196.418
PXI_C/BE1#: J2.E18 U11.21 | length 11.9
  TopLayer w0.152: U11.21@241.3,185.768 243.909,185.768 248.481,190.34 J2.E18@251.275,190.34
PXI_C/BE2#: J2.E11 U11.13 | length 11.9
  TopLayer w0.152: U11.13@241.3,181.768 245.572,181.768 J2.E11@251,176.34
PXI_C/BE3#: J2.A9 U11.9 | length 21.7
  TopLayer w0.152: U11.9@241.3,179.768 243.371,179.768 246.583,176.555 246.583,174.904 248.133,173.355 257.985,173.355 J2.A9@259,172.34
PXI_DEVSEL#: J2.A16 U11.18 | length 18.6
  TopLayer w0.152: U11.18@241.3,184.268 246.955,184.268 248.031,185.344 258.004,185.344 J2.A16@259,186.34
PXI_ENUM#: J2.C25 JP6.15
PXI_FRAME#: J2.B15 U10.10 | length 16.7
  BottomLayer w0.152: U10.10@241.3,183.46 246.994,183.46 247.625,182.829 255.489,182.829 J2.B15@257.089,184.429
PXI_GNT#: J2.E5 U10.22 | length 19.4
  BottomLayer w0.152: U10.22@241.3,177.46 243.164,177.46 243.992,176.632 243.992,169.342 247.701,165.633 249.707,165.633 J2.E5@251,164.34
PXI_HEALTHY#: J2.B4 JP6.14
PXI_IDSEL: J2.B9 U10.16 | length 22.8
  BottomLayer w0.152: U10.16@241.3,180.46 244.101,180.46 246.355,178.206 246.355,173.177 248.183,171.348 256.008,171.348 J2.B9@257,172.34
PXI_INTA#: J2.A3 U10.24 | length 32.1
  BottomLayer w0.152: U10.24@241.3,176.46 242.792,176.46 243.103,176.149 243.103,164.516 248.234,159.385 258.045,159.385 J2.A3@259.112,160.452
PXI_INTB#: J2.B3 JP6.16
PXI_INTC#: J2.C3 JP6.20
PXI_INTD#: J2.E3 JP6.13
PXI_INTP: J2.D4 JP6.3
PXI_INTS: J2.E4 JP6.11
PXI_IPMB_PWR: J2.A4 JP6.4
PXI_IPMB_SCL: J2.B17 JP6.10
PXI_IPMB_SDA: J2.C17 JP6.18
PXI_IRDY#: J2.C15 U11.16 | length 14.1
  TopLayer w0.152: U11.16@241.3,183.268 253.928,183.268 J2.C15@255,184.34
PXI_LOCK#: J2.E16
PXI_M66EN: J2.D21 JP6.7 R60.2
PXI_PAR: J2.D18 U10.7 | length 17.9
  BottomLayer w0.152: U10.7@241.3,184.96 247.165,184.96 247.599,185.395 253.492,185.395 254,185.903 254,189.34 J2.D18@253,190.34
PXI_PCLK: J2.D6 U11.2 | length 20.7
  TopLayer w0.152: U11.2@241.3,176.268 242.959,176.268 243.688,175.539 243.688,168.707 247.066,165.329 251.989,165.329 J2.D6@253,166.34
PXI_PERR#: J2.E17 U11.19 | length 11.2
  TopLayer w0.152: U11.19@241.3,184.768 246.642,184.768 247.752,185.877 248.537,185.877 J2.E17@251,188.34
PXI_REQ64#: J2.B25 JP6.8
PXI_REQ#: J2.A6 U11.3 | length 25.5
  TopLayer w0.152: U11.3@241.3,176.768 243.145,176.768 244.145,175.768 244.145,169.748 246.532,167.361 257.979,167.361 J2.A6@259,166.34
PXI_RST#: J2.C5 U10.23 | length 25
  BottomLayer w0.152: U10.23@241.3,176.96 243.08,176.96 243.586,176.454 243.586,167.538 247.752,163.373 254.033,163.373 J2.C5@255,164.34
PXI_SERR#: J2.A18 U11.20 | length 19.8
  TopLayer w0.152: U11.20@241.3,185.268 244.171,185.268 248.183,189.281 257.941,189.281 J2.A18@259,190.34
PXI_STOP#: J2.D16 U10.6 | length 12.9
  BottomLayer w0.152: U10.6@241.3,185.46 246.877,185.46 247.397,185.98 248.997,185.98 250.393,187.376 251.964,187.376 J2.D16@253,186.34
PXI_TCK: J2.A2 JP6.6
PXI_TDIO: J2.D2 J2.E2 | length 2
  BottomLayer w0.152: J2.E2@251,158.34 J2.D2@253,158.34
PXI_TMS: J2.C2 JP6.1
PXI_TRDY#: J2.E15 U10.9 | length 10.9
  BottomLayer w0.152: U10.9@241.3,183.96 247.205,183.96 247.955,183.21 249.87,183.21 J2.E15@251.293,184.633
PXI_TRST#: J2.C1
PXI_VIO: J2.C4 J2.C8 J2.C16 J2.C20 J2.C24
SCL: R87.2 U1.E4 U19.41
SDA: R88.2 U1.D3 U19.42
SDCKE: R30.6 U8.67
SERIN+: C2.2 JP8.1
SERIN-: C1.2 JP8.2
SEROUT+: C3.2 JP9.1
SEROUT-: C4.2 JP9.2
SYSTEM_RESET#: R71.1 U1.P4 U7.12 U18.1 U19.40
USER_LED0: DS1.1 U2.125
USER_LED1: DS2.1 U2.124
USER_LED2: DS3.1 U2.123
USER_LED3: DS4.1 U2.122
USER_LED4: DS5.1 U2.121
V1.4: C42.1 C43.1 C44.1 C50.1 C51.1 C52.1 C53.1 C60.1 C61.1 C62.1 C63.2 C70.1 C71.1 C72.1 C78.2 C79.1 C80.1 C81.1 C87.1 C88.1 C89.1 C90.2 C91.2 C92.2 C93.2 C94.2 C126.2 C138.1 C145.1 C148.1 C149.1 C151.1 L1.2 R69.2 R70.2 U1.AA6 U1.AA7 U1.AA20 U1.AA21 U1.F6 U1.F7 U1.F20 U1.F21 U1.G6 U1.G7 U1.G8 U1.G10 U1.G11 U1.G13 U1.G14 U1.G16 U1.G17 U1.G19 U1.G20 U1.G21 U1.H7 U1.H20 U1.K7 U1.K20 U1.L7 U1.L20 U1.M12 U1.M14 U1.N7 U1.N13 U1.N15 U1.N20 U1.P7 U1.P12 U1.P14 U1.P20 U1.R13 U1.R15 U1.T7 U1.T20 U1.U7 U1.U20 U1.W20 U1.Y6 U1.Y7 U1.Y8 U1.Y10 U1.Y11 U1.Y13 U1.Y14 U1.Y16 U1.Y17 U1.Y19 U1.Y20 U1.Y21
V1.5: C100.1 C101.1 C106.1 C107.1 C111.1 C112.1 C116.1 C117.1 C120.1 C121.1 C123.1 C124.1 C125.2 C137.1 FB1.1 FB2.1 U2.72 U2.81 U2.90 U2.97 U2.103 U2.110 U2.191 U2.198 U2.204 U2.211 U2.220 U2.229 U16.3
V2.5: C97.1 C103.1 C108.1 C132.2 C143.1 U2.130 U2.157 U2.172 U17.3
V3.3: C5.2 C6.2 C7.2 C8.2 C9.2 C10.2 C11.2 C12.2 C13.2 C14.2 C15.2 C16.2 C17.2 C18.2 C19.2 C20.2 C21.2 C22.2 C23.2 C24.2 C25.2 C26.2 C37.1 C38.1 C39.1 C40.1 C41.1 C45.1 C46.1 C47.1 C48.1 C49.1 C55.1 C56.1 C57.1 C58.1 C59.1 C65.1 C66.1 C67.1 C68.1 C69.1 C73.1 C74.1 C75.1 C76.1 C77.1 C82.1 C83.1 C84.1 C85.1 C86.1 C95.2 C98.1 C99.1 C104.1 C105.1 C109.1 C110.1 C114.1 C115.1 C119.1 C133.2 C135.1 C144.1 C147.1 C150.1 C152.1 C154.2 C156.2 C158.2 C162.2 C165.2 FB3.1 J1.5 JP3.7 JP4.4 JP5.4 R8.2 R14.2 R16.2 R26.2 R27.2 R29.2 R56.1 R57.1 R58.2 R61.2 R63.2 R71.2 R74.2 R78.2 R79.1 R80.2 R87.1 R88.1 U1.A2 U1.A25 U1.AA9 U1.AA12 U1.AA15 U1.AA18 U1.AB5 U1.AB7 U1.AB8 U1.AB10 U1.AB17 U1.AB19 U1.AB20 U1.AB22 U1.AC23 U1.AD24 U1.AE1 U1.AE2 U1.AE13 U1.AE25 U1.AE26 U1.AF2 U1.AF25 U1.B1 U1.B2 U1.B14 U1.B25 U1.B26 U1.C3 U1.C24 U1.D4 U1.D23 U1.E5 U1.E7 U1.E8 U1.E10 U1.E17 U1.E19 U1.E20 U1.E22 U1.F9 U1.F12 U1.F15 U1.F18 U1.G5 U1.G22 U1.H5 U1.H22 U1.J6 U1.J21 U1.K5 U1.K22 U1.M6 U1.M21 U1.N2 U1.P25 U1.R6 U1.R21 U1.U5 U1.U22 U1.V21 U1.W5 U1.W22 U1.W25 U1.Y5 U1.Y22 U2.9 U2.22 U2.51 U2.70 U2.92 U2.112 U2.189 U2.209 U2.231 U3.A1 U3.A3 U3.A8 U3.A10 U3.B1 U3.B10 U3.J1 U3.J10 U3.K1 U3.K3 U3.K8 U3.K10 U4.4 U5.3 U5.7 U5.8 U6.4 U7.37 U8.1 U8.3 U8.9 U8.15 U8.29 U8.35 U8.41 U8.43 U8.49 U8.55 U8.75 U8.81 U14.4 U18.5 U19.6 U19.17 U19.39 U20.1 U22.8 U23.4
V3.3A: C153.2 C155.2 C157.2 C159.2 U19.25 U19.28 U19.31 U19.36
V5: C32.2 C36.2 C96.2 C127.2 C134.1 C136.1 C139.1 C140.1 C146.1 C166.2 J3.1 R62.2 R64.1 R66.2 R73.2 U9.15 U10.15 U11.15 U14.2 U15.14 U15.15 U15.16 U16.1 U17.1
VCCA_PLL1: C128.2 C130.2 C141.1 FB1.2 U2.27
VCCA_PLL2: C129.2 C131.2 C142.1 FB2.2 U2.154
VP0_27MHZ: R76.2 U1.AF14
VP0_CLK1: U1.AF12 U19.4
VP0_HSYNC: U1.AE17 U19.8
VP0_VSYNC: U1.AC17 U19.7
VP0D2: U1.AF17 U19.16
VP0D3: U1.AF16 U19.15
VP0D4: U1.AE16 U19.14
VP0D5: U1.AD16 U19.13
VP0D6: U1.AC16 U19.12
VP0D7: U1.AB16 U19.11
VP0D8: U1.AE15 U19.10
VP0D9: U1.AD15 U19.9
XSPCLK: U1.R5 U22.2
XSPCS: U1.T4 U22.1
XSPDI: U1.R4 U22.4
XSPDO: U1.P5 U22.3
pads on no net: J1.6 J5.A1 J5.A2 J5.A3 J5.A4 J5.A5 J5.A6 J5.A7 J5.A8 J5.A9 J5.A10 J5.A11 J5.A12 J5.A13 J5.A14 J5.A15 J5.A16 J5.A17 J5.A18 J5.A19 J5.A20 J5.A21 J5.A22 J5.B1 J5.B2 J5.B3 J5.B4 J5.B5 J5.B6 J5.B7 J5.B8 J5.B9 J5.B10 J5.B11 J5.B12 J5.B13 J5.B14 J5.B15 J5.B16 J5.B17 J5.B18 J5.B19 J5.B20 J5.B21 J5.B22 J5.C1 J5.C2 J5.C3 J5.C4 J5.C5 J5.C6 J5.C7 J5.C8 J5.C9 J5.C10 J5.C11 J5.C12 J5.C13 J5.C14 J5.C15 J5.C16 J5.C17 J5.C18 J5.C19 J5.C20 J5.C21 J5.C22 J5.D1 J5.D2 J5.D3 J5.D4 J5.D5 J5.D6 J5.D7 J5.D8 J5.D9 J5.D10 J5.D11 J5.D12 J5.D13 J5.D14 J5.D15 J5.D16 J5.D17 J5.D18 J5.D19 J5.D20 J5.D21 J5.D22 J5.E1 J5.E2 J5.E3 J5.E4 J5.E5 J5.E6 J5.E7 J5.E8 J5.E9 J5.E10 J5.E11 J5.E12 J5.E13 J5.E14 J5.E15 J5.E16 J5.E17 J5.E18 J5.E19 J5.E20 J5.E21 J5.E22 JP3.3 JP3.5 JP4.6 JP4.7 JP4.8 JP6.17 JP6.19 R30.4 R30.5 S2.3 S2.4 U1.A4 U1.A5 U1.A7 U1.A9 U1.A10 U1.A11 U1.A13 U1.A17 U1.AA2 U1.AA3 U1.AA23 U1.AA24 U1.AA25 U1.AA26 U1.AB3 U1.AB11 U1.AB12 U1.AB13 U1.AB14 U1.AB15 U1.AB23 U1.AB24 U1.AB25 U1.AC1 U1.AC4 U1.AC6 U1.AC7 U1.AC8 U1.AC9 U1.AC10 U1.AC11 U1.AC12 U1.AC13 U1.AC14 U1.AC15 U1.AC19 U1.AC20 U1.AC21 U1.AC25 U1.AC26 U1.AD3 U1.AD5 U1.AD6 U1.AD7 U1.AD8 U1.AD9 U1.AD10 U1.AD11 U1.AD12 U1.AD13 U1.AD14 U1.AD17 U1.AD19 U1.AD20 U1.AD21 U1.AD22 U1.AD23 U1.AD25 U1.AD26 U1.AE5 U1.AE6 U1.AE7 U1.AE9 U1.AE11 U1.AE18 U1.AE20 U1.AE21 U1.AE22 U1.AE23 U1.AF3 U1.AF4 U1.AF5 U1.AF6 U1.AF8 U1.AF10 U1.AF18 U1.AF20 U1.AF21 U1.AF23 U1.AF24 U1.B8 U1.B9 U1.B10 U1.B11 U1.B12 U1.B15 U1.B16 U1.B17 U1.C7 U1.C8 U1.C9 U1.C10 U1.C11 U1.C12 U1.C15 U1.C16 U1.C17 U1.D6 U1.D7 U1.D8 U1.D9 U1.D10 U1.D11 U1.D12 U1.D15 U1.D16 U1.D17 U1.E11 U1.E12 U1.E13 U1.E14 U1.L22 U1.M5 U1.M22 U1.N22 U1.P22 U1.R22 U1.R25 U1.R26 U1.T22 U1.T23 U1.W7 U1.W23 U1.W24 U1.Y23 U1.Y24 U1.Y25 U1.Y26 U2.108 U2.113 U2.114 U2.115 U2.116 U2.117 U2.118 U2.119 U2.120 U2.126 U2.127 U2.128 U2.131 U2.138 U2.139 U2.140 U2.141 U2.143 U2.144 U2.152 U2.156 U2.158 U2.159 U2.160 U2.161 U2.162 U2.163 U2.170 U2.175 U2.176 U2.181 U2.182 U2.183 U2.184 U3.B8 U3.H10 U3.J9 U4.1 U6.1 U7.9 U7.10 U7.13 U7.14 U7.15 U7.30 U7.32 U7.34 U7.36 U7.39 U7.41 U7.43 U8.14 U8.30 U8.57 U8.69 U8.70 U8.73 U9.1 U9.2 U9.3 U9.4 U9.5 U9.6 U9.7 U9.9 U9.10 U9.11 U9.12 U9.36 U9.37 U9.38 U9.39 U9.40 U9.42 U9.43 U9.44 U9.45 U9.46 U10.1 U11.1 U14.5 U16.4 U17.4 U19.1 U19.20 U19.22 U19.23 U19.24 U19.26 U19.27 U19.29 U19.34 U19.37 U19.43 U21.1 U22.6 U22.7 U23.1
copper on no net:
  other v2: 108.23,228.046 108.23,234.946

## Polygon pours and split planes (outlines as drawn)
GND on GROUND (split plane): 102.108,152.908 102.108,251.891 261.086,251.891 261.086,152.908

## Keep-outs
KeepOutLayer:
  lines w0.203: 260.096,158.039 260.096,155.423 ; 260.096,243.154 260.096,249.403 256.286,249.403 107.696,249.403 107.696,244.323 103.251,244.323 103.251,160.503 107.696,160.503 107.696,155.423 256.286,155.423 260.096,155.423 ; 260.096,244.323 260.096,160.503 260.096,155.423

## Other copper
MidLayer1:
  text ".G1" at 253.975,256.21 h2.29
MidLayer2:
  text ".G2" at 253.975,256.21 h2.29
MidLayer3:
  text ".G3" at 253.975,256.21 h2.29
MidLayer4:
  text ".G4" at 253.975,256.21 h2.29
MidLayer5:
  text ".G5" at 253.975,256.21 h2.29
MidLayer6:
  text ".G6" at 253.975,256.21 h2.29
MidLayer7:
  text ".G7" at 253.975,256.21 h2.29
MidLayer8:
  text ".G8" at 253.975,256.21 h2.29
BottomLayer:
  text "P/N XXXXXX-XXX REV A" at 135.128,257.48 h1.91

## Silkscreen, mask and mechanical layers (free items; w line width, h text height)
TopOverlay:
  circle w0.254: c105.156,157.912 r2.857
  circle w0.254: c105.156,246.812 r2.857
  lines w0.254: 136.972,272.617 ccw(c138.201,273.621) 136.975,272.614
  text "CVBS" at 105.359,234.467 h1.52
  text "LVDS OUT" at 104.191,226.924 h1.52
  text "LVDS IN" at 103.607,193.243 h1.52
BottomOverlay:
  text "LVDS" at 34.061,226.974 h0.76
Mechanical1:
  the board outline again, w0.508
Mechanical4:
  lines w0.5: 261.875,232.725 268.125,232.725 ; 261.9,202.725 264.8,202.725 ; 262.025,246.7 268.275,246.7
  text ".Pcb_File_Name_No_Path" at 205.715,261.036 h2.29
  text ".Printout_Name" at 205.715,256.21 h2.29
  text "90.45" at 270.15,245.925 h1.52
  text "76.45" at 270.225,231.9 h1.52
  text "46.45" at 265.5,198.15 h1.52

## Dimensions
105.156,151.892 to 101.6,152.4 on Mechanical4
101.092,157.912 to 101.6,152.4 on Mechanical4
